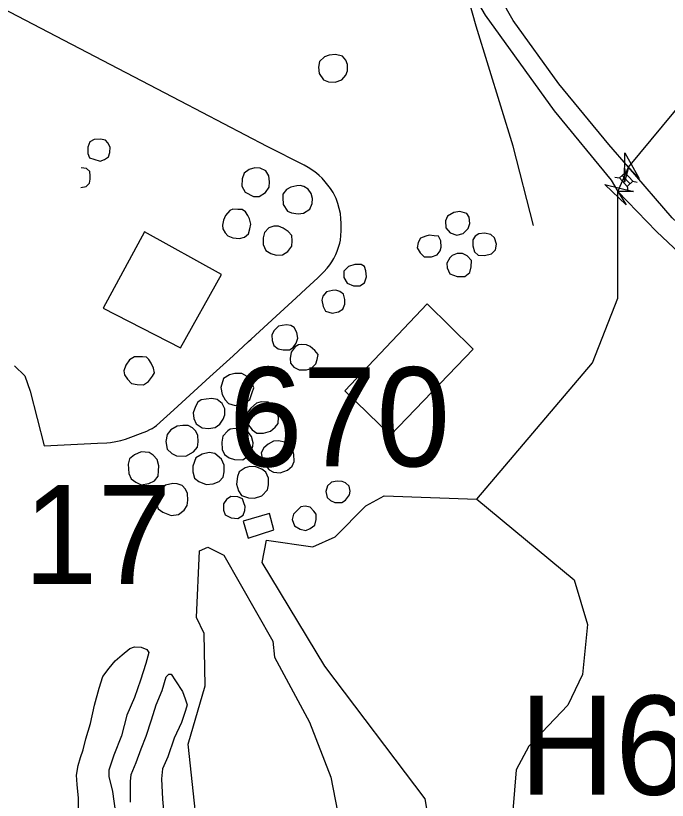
# Model space of a CAD drawing. Extents: x 1383679 to 1536984, y 460658 to 651027.
# Drawn here: x 1438807 to 1441502, y 483158 to 486404 of the extents above; entities that cross this region are included whole.
import ezdxf

# ---------------------------------------------------------------- set-up
doc = ezdxf.new("R2010")
doc.units = 0
for name, color, linetype in [('Exist Hydrographic Creek Single Shore', 7, 'Continuous'), ('Exist Hydrographic Misc Water Feature', 7, 'Continuous'), ('Exist Road Non-System Type 51', 7, 'Continuous'), ('Exist Road Primary Interstate Divided Center Attributed', 7, 'Continuous'), ('Exist Road Primary Interstate Structure Standard Bridge CELL', 7, 'Continuous'), ('Exist Road Primary US Structure Non-Sys NCDOT Number Label', 7, 'Continuous'), ('Exist Road Secondary Structure Standard Bridge Attributed CELL', 7, 'Continuous'), ('Exist Road Secondary Structure Standard Bridge Number Label', 7, 'Continuous'), ('Exist Utilities Electrical Transmission Line', 7, 'Continuous')]:
    doc.layers.add(name, color=color, linetype=linetype)

msp = doc.modelspace()

# ---------------------------------------------------------------- linework, layer by layer
at = {"layer": 'Exist Hydrographic Creek Single Shore'}
for points in [[(1440714.2, 484403.2), (1441192.2, 484968), (1441297.1, 485235.1), (1441297.1, 485676.3), (1441341, 485777.5), (1441756.5, 486277.7), (1442102.4, 487194.6), (1442253.2, 487375.7), (1442480.2, 487505.7), (1442780.2, 487965.7), (1442833.2, 488132.1), (1443490.2, 489395.8), (1443517.3, 489946.6)], [(1439010.2, 482392.6), (1439125.1, 482304.9), (1439359.2, 482333.1), (1440060.1, 482322.2), (1440227.2, 482384.5), (1440312.2, 482468.2), (1440410.2, 482774.7), (1440530.1, 482995.5), (1440500.1, 483163.5), (1440085.2, 483713.5), (1439826.2, 484142.1), (1439844.1, 484233.6), (1440036.2, 484206.8), (1440128.1, 484247.7), (1440255.2, 484376.3), (1440331.1, 484417.5), (1440714.2, 484403.2)], [(1440714.2, 484403.2), (1441117.2, 484070.2), (1441172.2, 483885.3), (1441151.1, 483678.9), (1441091.2, 483552.1), (1440929.2, 483381.3), (1440877.2, 483283.9), (1440856.2, 483031.6)]]:
    msp.add_lwpolyline(points, dxfattribs=at)
at = {"layer": 'Exist Hydrographic Misc Water Feature'}
for points in [[(1440130.3, 486242.9), (1440104.2, 486241), (1440084.1, 486234), (1440063.8, 486213.9), (1440059.3, 486190.2), (1440062.9, 486163.9), (1440080.4, 486138), (1440100.3, 486129.5), (1440128.3, 486128.9), (1440156.4, 486138.2), (1440172.9, 486158.3), (1440179.1, 486175.5), (1440179.6, 486201.7), (1440172, 486219.9), (1440158.2, 486236.6), (1440130.3, 486242.9)], [(1439158.5, 485892.7), (1439132.4, 485891.6), (1439114.3, 485881.3), (1439105.9, 485860.1), (1439105.3, 485833.8), (1439113, 485815.6), (1439131, 485809.6), (1439156.8, 485802.4), (1439175, 485808.6), (1439191.2, 485819.8), (1439197.4, 485837.7), (1439197.9, 485859.9), (1439188.2, 485878.1), (1439178.3, 485888.2), (1439158.5, 485892.7)], [(1439076.4, 485692.5), (1439098.8, 485697.7), (1439113.1, 485711.4), (1439115.4, 485727.8), (1439115.7, 485741.7), (1439114.1, 485759.8), (1439100.2, 485771.6), (1439078, 485774.5)], [(1439772.4, 485767.1), (1439752.1, 485751.9), (1439743.7, 485728.2), (1439743.1, 485697.9), (1439756.8, 485673.9), (1439790.3, 485655.1), (1439814.4, 485656.3), (1439840.8, 485672.2), (1439855.1, 485694), (1439857.6, 485716.1), (1439854.1, 485741.6), (1439842.4, 485762.4), (1439818.6, 485772.7), (1439796.6, 485774.8), (1439772.4, 485767.1)], [(1439969.3, 485699.9), (1439945.2, 485694.7), (1439927, 485684.4), (1439912.6, 485664.9), (1439912.4, 485651), (1439913.9, 485623.1), (1439931.3, 485594.8), (1439947.3, 485587.9), (1439975.2, 485584.1), (1439997.2, 485586.9), (1440023.6, 485602.8), (1440034, 485626.4), (1440034.3, 485646.9), (1440028.7, 485668.4), (1440017.1, 485686.7), (1439999.3, 485697.7), (1439983.3, 485701.3), (1439969.3, 485699.9)], [(1439693.2, 485597.2), (1439674.9, 485577), (1439666.6, 485557.5), (1439662.3, 485537), (1439663.8, 485521.5), (1439673.5, 485504.8), (1439685.3, 485493.1), (1439705.2, 485484.5), (1439733.2, 485482.3), (1439753.3, 485487.6), (1439769.6, 485501.3), (1439776, 485521.7), (1439780.4, 485541.2), (1439774.6, 485563.5), (1439766.9, 485577.6), (1439757.2, 485591.8), (1439743.5, 485601.9), (1439725.4, 485602.2), (1439705.4, 485602.7), (1439693.2, 485597.2)], [(1440643.6, 485593.6), (1440619.6, 485590), (1440593.3, 485574.1), (1440584.9, 485554.6), (1440586.4, 485526.7), (1440604.1, 485505.8), (1440631.9, 485495.4), (1440658, 485503), (1440678.4, 485523.1), (1440684.8, 485544.4), (1440683.2, 485570.7), (1440673.6, 485584.8), (1440643.6, 485593.6)], [(1439874.2, 485533.6), (1439854.1, 485525.8), (1439835.6, 485506.5), (1439831.3, 485484.4), (1439830.7, 485456.6), (1439842.4, 485431.7), (1439862.1, 485419.8), (1439884, 485413.6), (1439910.1, 485414.7), (1439932.3, 485428.2), (1439948.7, 485450), (1439951.1, 485472.1), (1439949.5, 485494.3), (1439933.9, 485510.3), (1439914.1, 485524.6), (1439894.3, 485533.2), (1439874.2, 485533.6)], [(1439658.5, 485333.6), (1439339.6, 485509.1), (1439169.7, 485194.1), (1439488.9, 485030.1), (1439658.5, 485333.6)], [(1440503.8, 485492.2), (1440481.6, 485482.8), (1440471.2, 485465), (1440466.9, 485442.9), (1440480.5, 485422.1), (1440496.2, 485406.2), (1440526.3, 485405.6), (1440550.4, 485415), (1440562.7, 485431.1), (1440567, 485446.6), (1440565.4, 485472.9), (1440555.8, 485491.2), (1440537.7, 485493.2), (1440517.7, 485496), (1440503.8, 485492.2)], [(1440707.8, 485492.2), (1440697.6, 485476.9), (1440697.2, 485452.2), (1440704.7, 485426.6), (1440720.3, 485412.4), (1440746.4, 485411.9), (1440774.5, 485418.7), (1440790.9, 485434.7), (1440795.2, 485458.4), (1440787.8, 485484.9), (1440771.9, 485499.2), (1440746.1, 485503.8), (1440722.1, 485501.8), (1440707.8, 485492.2)], [(1440602.1, 485402.4), (1440589.7, 485380.5), (1440591.4, 485360), (1440602.8, 485335.9), (1440632.8, 485325.5), (1440664.8, 485324.9), (1440685.1, 485340.9), (1440691.4, 485364.5), (1440692, 485390.8), (1440674.3, 485410.8), (1440654.5, 485419.4), (1440632.5, 485419.9), (1440612.3, 485412.1), (1440602.1, 485402.4)], [(1440209.5, 485375), (1440183.3, 485365.7), (1440164.9, 485346.4), (1440164.4, 485320.1), (1440178.1, 485297.7), (1440203.9, 485285.7), (1440229.9, 485286.8), (1440250.1, 485298.7), (1440258.6, 485324), (1440255, 485348.7), (1440249.3, 485366.8), (1440235.4, 485374.5), (1440209.5, 485375)], [(1440117.5, 485266.9), (1440093.3, 485261.7), (1440077, 485244), (1440072.8, 485227.6), (1440078.3, 485201.3), (1440088, 485181.4), (1440115.7, 485172.6), (1440141.8, 485178.7), (1440160.1, 485189.8), (1440168.4, 485210.1), (1440168.9, 485229.8), (1440163.2, 485252.1), (1440147.4, 485262.2), (1440131.5, 485268.3), (1440117.5, 485266.9)], [(1440699.3, 485024.7), (1440508.6, 485211.5), (1440167.9, 484851.5), (1440356.6, 484668), (1440699.3, 485024.7)], [(1439926.8, 485124.7), (1439908.7, 485122.6), (1439894.6, 485118.8), (1439874.4, 485099.5), (1439866, 485081.6), (1439867.6, 485059.4), (1439875.2, 485039.6), (1439893, 485025.3), (1439912.8, 485020.8), (1439939, 485021.9), (1439955.1, 485031.4), (1439967.4, 485049.2), (1439973.7, 485069.6), (1439970.3, 485093.5), (1439958.6, 485113.4), (1439944.7, 485121.9), (1439926.8, 485124.7)], [(1439963.2, 485033.7), (1439946.8, 485011.9), (1439942.3, 484985.7), (1439943.9, 484966), (1439957.6, 484950.1), (1439979.5, 484939), (1440009.4, 484938.4), (1440029.5, 484944.6), (1440048, 484963.9), (1440054.2, 484981.8), (1440058.5, 485002.3), (1440044.9, 485018.1), (1440025.2, 485034.9), (1440009.3, 485042.7), (1439989.3, 485043), (1439977.3, 485041.6), (1439963.2, 485033.7)], [(1439332.1, 484993.1), (1439298.1, 484992.1), (1439277.8, 484980.2), (1439263.4, 484958.4), (1439254.9, 484934.7), (1439256.7, 484918.3), (1439270.4, 484899.9), (1439286, 484881.6), (1439310, 484877.8), (1439335.9, 484877.3), (1439356.2, 484890.9), (1439372.7, 484912.7), (1439380.9, 484926.4), (1439377.2, 484946.2), (1439367.6, 484966.1), (1439357.9, 484981.1), (1439348.1, 484991.1), (1439332.1, 484993.1)], [(1439666.6, 484902.7), (1439655.9, 484865.1), (1439661.4, 484837.1), (1439673, 484814.7), (1439686.8, 484798.8), (1439714.6, 484791.7), (1439750.7, 484797.6), (1439775.2, 484816.7), (1439785.6, 484844.5), (1439792, 484864.8), (1439780.5, 484893), (1439764.8, 484911.3), (1439743, 484923.3), (1439713, 484923.9), (1439690.9, 484918.5), (1439666.6, 484902.7)], [(1439550.5, 484786.8), (1439542, 484761.5), (1439543.5, 484736.9), (1439553.2, 484715.4), (1439578.8, 484698.4), (1439604.8, 484696.3), (1439632.8, 484699.8), (1439651.2, 484713.4), (1439665.6, 484735.3), (1439671.9, 484753.2), (1439672.3, 484777), (1439660.7, 484799.4), (1439641, 484815.4), (1439619, 484819.9), (1439595, 484817.9), (1439574.9, 484815), (1439560.8, 484804.6), (1439550.5, 484786.8)], [(1439780.4, 484780.5), (1439766.1, 484762.8), (1439763.8, 484741.5), (1439765.3, 484715.2), (1439784.8, 484691), (1439804.5, 484676.7), (1439832.6, 484676.1), (1439860.7, 484685.4), (1439881, 484701.4), (1439893.3, 484716.7), (1439893.9, 484743), (1439884.2, 484772.7), (1439870.6, 484793.5), (1439850.9, 484805.4), (1439822.9, 484806), (1439802.8, 484800.6), (1439780.4, 484780.5)], [(1439521, 484707.8), (1439498.9, 484708.3), (1439474.9, 484706.3), (1439448.6, 484691.2), (1439434.3, 484671), (1439427.8, 484641.6), (1439433.2, 484611.1), (1439452.8, 484592.7), (1439472.6, 484582.4), (1439510.6, 484581.6), (1439543, 484599), (1439559.4, 484619.2), (1439561.8, 484640.5), (1439560.3, 484668.4), (1439550.6, 484686.7), (1439538.8, 484699.2), (1439521, 484707.8)], [(1439684.7, 484686.5), (1439664.2, 484664.7), (1439659.8, 484639.4), (1439661.2, 484609), (1439670.9, 484589.1), (1439690.7, 484574.7), (1439712.5, 484567.8), (1439746.4, 484567), (1439768.8, 484583), (1439779, 484596.8), (1439787.7, 484622.9), (1439789.8, 484636.8), (1439782.2, 484663.2), (1439768.6, 484680.7), (1439748.8, 484693.4), (1439714.8, 484695.7), (1439694.8, 484692.8), (1439684.7, 484686.5)], [(1439874, 484643.3), (1439851.8, 484631.4), (1439833.4, 484616.2), (1439823, 484595.9), (1439828.5, 484563.8), (1439838.2, 484545.5), (1439855.8, 484525.5), (1439873.7, 484515.3), (1439901.6, 484512.2), (1439931.8, 484523.9), (1439950.1, 484540), (1439958.5, 484559.5), (1439957, 484589.9), (1439951.4, 484611.3), (1439939.8, 484629.6), (1439919.9, 484639.9), (1439894, 484644.5), (1439874, 484643.3)], [(1439326.9, 484599.3), (1439298.6, 484587.5), (1439278.4, 484569.9), (1439272, 484547.9), (1439275.2, 484510.1), (1439284.9, 484487.7), (1439304.6, 484473.4), (1439326.4, 484463.1), (1439358.5, 484468.2), (1439380.8, 484480), (1439397, 484499.4), (1439397.5, 484521.6), (1439399.9, 484542), (1439392.4, 484567.6), (1439376.6, 484586), (1439358.8, 484596.2), (1439326.9, 484599.3)], [(1439552.6, 484575.1), (1439539.9, 484540.8), (1439539.5, 484517.1), (1439546.9, 484490.7), (1439564.8, 484476.4), (1439594.5, 484464.3), (1439624.6, 484467.7), (1439648.8, 484477.1), (1439665.1, 484494.9), (1439669.5, 484516.9), (1439670.1, 484544.8), (1439658.5, 484568.8), (1439631, 484593.2), (1439606.9, 484596.1), (1439578.8, 484590.1), (1439552.6, 484575.1)], [(1439731.7, 484517.3), (1439725.2, 484497.7), (1439720.6, 484465.8), (1439728.1, 484437.8), (1439741.7, 484419.5), (1439769.6, 484409), (1439795.6, 484408.5), (1439825.8, 484417.8), (1439848.3, 484441.9), (1439852.6, 484463.2), (1439853.2, 484491.1), (1439841.7, 484515.9), (1439825.8, 484527.7), (1439800, 484538.1), (1439776.1, 484538.5), (1439755.9, 484533.2), (1439731.7, 484517.3)], [(1439456.6, 484468.7), (1439426.5, 484461.1), (1439406.1, 484443.4), (1439389.7, 484420), (1439387.1, 484392.1), (1439396.7, 484364), (1439416.4, 484349.7), (1439450.2, 484336.7), (1439480.3, 484340.2), (1439504.6, 484357.7), (1439516.9, 484377.2), (1439519.3, 484399.3), (1439517.8, 484427.2), (1439510.1, 484445.4), (1439496.4, 484459.6), (1439474.5, 484466.7), (1439456.6, 484468.7)], [(1440110.9, 484471.1), (1440096.7, 484459.1), (1440090.2, 484435.4), (1440095.8, 484410.7), (1440109.6, 484398.9), (1440127.4, 484390.3), (1440155.4, 484389.8), (1440171.6, 484399.3), (1440188.1, 484421.1), (1440190.4, 484437.5), (1440186.7, 484457.3), (1440171, 484471.5), (1440157.1, 484477.5), (1440137.1, 484477.9), (1440113, 484474.4), (1440110.9, 484471.1)], [(1439697.6, 484414.6), (1439679.5, 484402.6), (1439667.1, 484384.8), (1439666.7, 484358.6), (1439674.3, 484338.8), (1439698.1, 484325.9), (1439726, 484323.7), (1439748.3, 484337.2), (1439754.6, 484356.8), (1439756.9, 484373.2), (1439751.3, 484388.9), (1439745.6, 484405.4), (1439725.7, 484414), (1439697.6, 484414.6)], [(1439974.9, 484361.4), (1439956.5, 484341.3), (1439950.1, 484319.2), (1439959.7, 484293.6), (1439983.4, 484279.2), (1440007.3, 484274.6), (1440025.4, 484282.4), (1440043.8, 484296), (1440050.1, 484319.7), (1440050.5, 484341.8), (1440040.8, 484354.3), (1440025, 484370.2), (1440005.1, 484374.7), (1439987.1, 484372.6), (1439974.9, 484361.4)], [(1439856.5, 484344.9), (1439747.9, 484313.4), (1439768.6, 484242.5), (1439875.2, 484277.2), (1439856.5, 484344.9)], [(1439739.1, 482578.1), (1439649.1, 482662), (1439577.1, 482863.7), (1439520.1, 483390), (1439591.1, 483631.5), (1439587.1, 483848.2), (1439555.1, 483914.5), (1439568.1, 484189.9), (1439602.2, 484205.7), (1439668.2, 484171.5), (1439870.2, 483816.3), (1439877.1, 483750.5), (1440022.1, 483481.7), (1440110.2, 483253.4), (1440148.1, 483062.3), (1440143.1, 482786.7), (1440100.1, 482705.5), (1439948.1, 482606.8), (1439739.1, 482578.1)], [(1439069.1, 483079), (1439066.6, 483166.8), (1439061.7, 483223.6), (1439058.4, 483261.4), (1439065.2, 483301.5), (1439075.7, 483334.9), (1439086.3, 483366.7), (1439097.1, 483412.4), (1439116.3, 483476), (1439133.6, 483552), (1439153, 483622.2), (1439167.8, 483669.5), (1439194.4, 483705), (1439219, 483734.9), (1439247.4, 483759.8), (1439280.1, 483785.4), (1439298.2, 483793.2), (1439326.2, 483791), (1439350, 483782.4), (1439357.8, 483769.8), (1439345, 483724.2), (1439323.6, 483654.9), (1439298.3, 483583.1), (1439266.9, 483509.9), (1439245.5, 483424.2), (1439213.9, 483344.4), (1439192.8, 483283.3), (1439192.3, 483257.1), (1439207.2, 483194.4), (1439219.6, 483104.7)], [(1439282.4, 483151), (1439282, 483235.5), (1439284.5, 483265), (1439305.4, 483314.7), (1439326.4, 483370.9), (1439347.4, 483423.8), (1439368.6, 483491.5), (1439387.9, 483553.5), (1439412.9, 483612.8), (1439430, 483669.1), (1439440.2, 483680.4), (1439450.2, 483680.2), (1439467.7, 483651.9), (1439496.9, 483607.9), (1439508.4, 483577.3), (1439515.9, 483553.3), (1439509.4, 483529.7), (1439492.6, 483480), (1439463.4, 483415.7), (1439436, 483338.3), (1439415.1, 483288.6), (1439410.3, 483246.9), (1439414.7, 483163.1), (1439426.4, 483028.3)]]:
    msp.add_lwpolyline(points, dxfattribs=at)
at = {"layer": 'Exist Road Non-System Type 51'}
msp.add_lwpolyline([(1438802.4, 484955.7), (1438845.9, 484913.4), (1438867.7, 484850.1), (1438925.7, 484624.9), (1439146, 484635.3), (1439183.8, 484636.2), (1439200, 484638.3), (1439221.4, 484642.1), (1439241.6, 484646.6), (1439260.9, 484652.5), (1439283.7, 484659.9), (1439324.2, 484674.9), (1439350.4, 484685.7), (1439362.2, 484691.5), (1439371.3, 484696.1), (1439379.4, 484701.3), (1439389.4, 484709.1), (1439461.4, 484773.3), (1439610.3, 484910), (1439706.9, 484996.6), (1439769.8, 485055.9), (1439780.8, 485066), (1439884.4, 485160.4), (1439967.7, 485237), (1440006.6, 485274), (1440056.5, 485319.9), (1440081.1, 485343.5), (1440095.8, 485359.9), (1440105.9, 485373.5), (1440114.2, 485385.4), (1440122.3, 485398.9), (1440131, 485416.1), (1440136.8, 485430.3), (1440142.5, 485446), (1440147.6, 485462.4), (1440150.1, 485475.5), (1440153.7, 485514), (1440153.7, 485545.8), (1440152.4, 485563), (1440149.9, 485585.6), (1440145.4, 485606.6), (1440140, 485626.4), (1440132.3, 485648), (1440126.2, 485661.1), (1440119.8, 485672.1), (1440109.2, 485688.5), (1440087.6, 485717.1), (1440075, 485731.3), (1440063, 485742.4), (1440050.7, 485752.9), (1440040.1, 485760.6), (1440016.8, 485775.5), (1439999.9, 485784.9), (1439847.6, 485862.9), (1439489.3, 486049.5), (1438332.3, 486653.7)], dxfattribs=at)
at = {"layer": 'Exist Road Primary Interstate Divided Center Attributed'}
for points in [[(1439939.5, 488181.9), (1439984.3, 487996.2), (1440112.3, 487653.5), (1440253.1, 487306.3), (1440384.3, 487030.9), (1440749.1, 486406.5), (1441034, 486009.6), (1441270.3, 485722.8), (1441297.1, 485676.3)], [(1441341, 485777.5), (1441260.4, 485871.2), (1441054, 486122.1), (1440864.3, 486384.1), (1440483.5, 487053.4), (1440351.8, 487312.8), (1440176.3, 487736.8), (1440064.3, 488069.8), (1440029.1, 488201.1)], [(1442402.3, 484797.7), (1442221.8, 484947.5), (1442036.8, 485087.5), (1441522.1, 485567.1), (1441341, 485777.5)], [(1441297.1, 485676.3), (1441457.6, 485510.7), (1441984, 485015.2), (1442209.5, 484828.6), (1442371.1, 484694.8)]]:
    msp.add_lwpolyline(points, dxfattribs=at)
at = {"layer": 'Exist Road Primary Interstate Structure Standard Bridge CELL'}
for p, q in [((1441324.7, 485772.8), (1441327, 485754.1)), ((1441285.4, 485736.4), (1441303.8, 485732.6)), ((1441315.4, 485743.3), (1441347.7, 485708.5)), ((1441359.2, 485719.2), (1441377.7, 485715.4)), ((1441336.3, 485697.9), (1441338.7, 485679.3))]:
    msp.add_line(p, q, dxfattribs=at)
msp.add_lwpolyline([(1441303.8, 485732.6), (1441336.1, 485697.7), (1441359.3, 485719.2), (1441327, 485754.1)], close=True, dxfattribs=at)
at = {"layer": 'Exist Road Secondary Structure Standard Bridge Attributed CELL'}
for points in [[(1441324.9, 485714.6), (1441325.6, 485836.5), (1441385.9, 485730.5), (1441341, 485777.5)], [(1441331.6, 485621.2), (1441243.8, 485705.8), (1441362.1, 485676.5), (1441297.1, 485676.3)]]:
    msp.add_lwpolyline(points, close=True, dxfattribs=at)
at = {"layer": 'Exist Utilities Electrical Transmission Line'}
msp.add_lwpolyline([(1440949, 485535.8), (1440865, 485863.4), (1440711.9, 486360.3), (1440595.3, 486772.7), (1440349.7, 487015.3), (1439919.2, 487425.3), (1439596.7, 487737.4), (1439313.6, 488018.6), (1439124.8, 488190.1)], dxfattribs=at)

# ---------------------------------------------------------------- texts
at = {"layer": 'Exist Road Primary US Structure Non-Sys NCDOT Number Label'}
msp.add_text('H651', height=410.1, dxfattribs=at).set_placement((1440890.7, 483181.1))
at = {"layer": 'Exist Road Secondary Structure Standard Bridge Number Label'}
for s, p in [('670', (1439688.9, 484539.3)), ('17', (1438840.4, 484052.4))]:
    msp.add_text(s, height=410.1, dxfattribs=at).set_placement(p)

doc.saveas('drawing.dxf')
